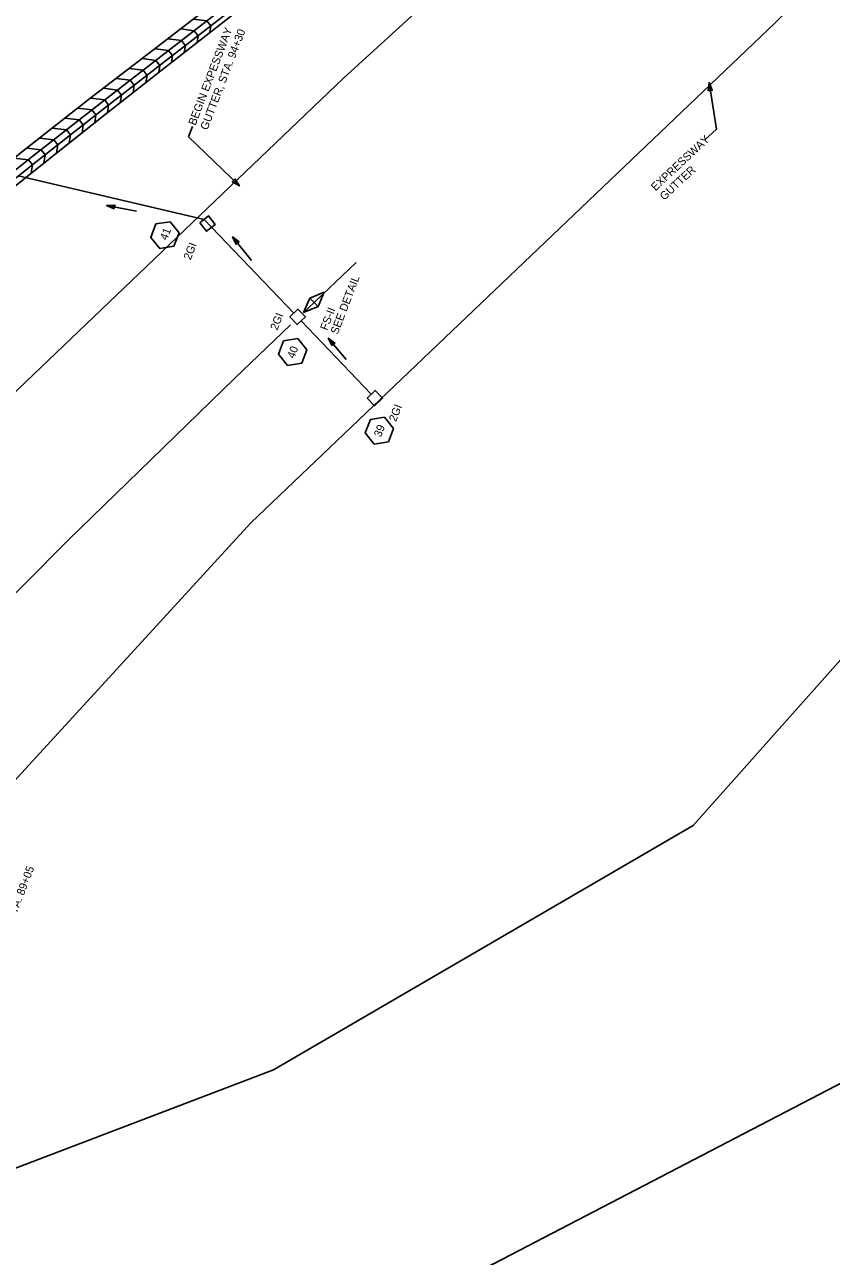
# Model space of a CAD drawing. Extents: x 2384780 to 2405432, y 547869 to 573706.
# Drawn here: x 2396264 to 2396768, y 557527 to 558297 of the extents above; entities that cross this region are included whole.
import ezdxf

# ---------------------------------------------------------------- set-up
doc = ezdxf.new("R2010")
doc.units = 0
for name, color, linetype in [('Old_Level_1', 7, 'Continuous'), ('Old_Level_18', 7, 'Continuous'), ('Old_Level_19', 7, 'Continuous'), ('Old_Level_5', 7, 'Continuous'), ('Old_Level_62', 7, 'Continuous'), ('Old_Level_63', 7, 'Continuous'), ('Old_Level_9', 7, 'Continuous'), ('Prop Drainage Box Number Symbol CELL', 7, 'Continuous')]:
    doc.layers.add(name, color=color, linetype=linetype)

# ---------------------------------------------------------------- blocks, each defined once
blk = doc.blocks.new('FALSUP')
at = {"layer": 'Old_Level_9'}
for p, q in [((0, 0.07375), (-0.181, 0.00325)), ((-0.181, 0.00325), (0, -0.07375)), ((0, -0.07375), (0, 0.07375)), ((0.1775, 0), (0, 0.07375)), ((0, -0.07375), (0.1775, 0))]:
    blk.add_line(p, q, dxfattribs=at)

msp = doc.modelspace()

# ---------------------------------------------------------------- linework, layer by layer
at = {"layer": 'Old_Level_1'}
for p, q in [((2396260.04, 558202.17), (2396376.28, 558175.01)), ((2396432.38, 558116.5), (2396376.28, 558175.01)), ((2396480.66, 558065.71), (2396437.01, 558111.65))]:
    msp.add_line(p, q, dxfattribs=at)
at = {"layer": 'Old_Level_18'}
for p, q in [((2396344.88, 558281.12), (2396384.67, 558311.83)), ((2396388.81, 558307.49), (2396349.08, 558276.71)), ((2396391.56, 558304.59), (2396351.83, 558273.81)), ((2396393.55, 558302.5), (2396353.99, 558271.54)), ((2396304.86, 558250.55), (2396344.88, 558281.12)), ((2396349.08, 558276.71), (2396309.25, 558245.94)), ((2396351.83, 558273.81), (2396312.01, 558243.04)), ((2396314.38, 558240.54), (2396353.99, 558271.54)), ((2396264.98, 558219.35), (2396304.86, 558250.55)), ((2396309.25, 558245.94), (2396269.4, 558214.72)), ((2396312.01, 558243.04), (2396272.17, 558211.83)), ((2396314.38, 558240.54), (2396274.69, 558209.19)), ((2396225.04, 558187.64), (2396264.98, 558219.35)), ((2396272.17, 558211.83), (2396232.32, 558180.1)), ((2396274.69, 558209.19), (2396234.73, 558177.59))]:
    msp.add_line(p, q, dxfattribs=at)
for points in [[(2396110.11, 558084.02), (2396149.75, 558117.8), (2396189.58, 558150.76), (2396229.54, 558182.98), (2396269.4, 558214.72), (2396309.25, 558245.94), (2396349.08, 558276.71), (2396388.81, 558307.49), (2396428.7, 558338.09), (2396468.11, 558369.2), (2396507.43, 558400.42), (2396546.46, 558431.93), (2396585.2, 558463.75), (2396623.66, 558495.86), (2396661.09, 558527.62)], [(2396369.6, 558300.19), (2396378.01, 558299.13), (2396380.49, 558295.93), (2396379.85, 558291.78)], [(2396361.58, 558294.01), (2396370.02, 558292.94), (2396372.5, 558289.74), (2396371.85, 558285.52)], [(2396353.57, 558287.82), (2396362.03, 558286.75), (2396364.51, 558283.55), (2396363.85, 558279.26)], [(2396345.55, 558281.64), (2396354.04, 558280.56), (2396356.52, 558277.36), (2396355.85, 558272.99)], [(2396329.41, 558269.3), (2396338.05, 558268.19), (2396340.53, 558264.99), (2396339.82, 558260.45)], [(2396337.49, 558275.47), (2396346.05, 558274.37), (2396348.52, 558271.17), (2396347.84, 558266.72)], [(2396321.34, 558263.13), (2396330.05, 558262.01), (2396332.53, 558258.81), (2396331.81, 558254.18)], [(2396313.26, 558256.96), (2396322.06, 558255.84), (2396324.53, 558252.63), (2396323.8, 558247.91)], [(2396305.19, 558250.8), (2396314.06, 558249.66), (2396316.53, 558246.45), (2396315.79, 558241.64)], [(2396289.21, 558238.3), (2396298.12, 558237.22), (2396300.62, 558234.04), (2396299.89, 558229.09)], [(2396297.18, 558244.54), (2396306.08, 558243.46), (2396308.57, 558240.27), (2396307.85, 558235.38)], [(2396281.24, 558232.07), (2396290.17, 558230.99), (2396292.66, 558227.8), (2396291.92, 558222.8)], [(2396273.27, 558225.84), (2396282.21, 558224.76), (2396284.71, 558221.57), (2396283.96, 558216.51)], [(2396265.3, 558219.61), (2396274.26, 558218.52), (2396276.75, 558215.34), (2396276, 558210.22)], [(2396257.33, 558213.28), (2396266.32, 558212.26), (2396268.84, 558209.1), (2396268.13, 558204)]]:
    msp.add_lwpolyline(points, dxfattribs=at)
at = {"layer": 'Old_Level_19'}
for points in [[(2396438.32, 558116.7), (2396441.15, 558119.4), (2396471.41, 558148.04)], [(2396059.34, 557724.13), (2396157.46, 557835.98), (2396196.83, 557878.26), (2396236.9, 557919.92), (2396291.11, 557974.52), (2396395.24, 558075.64), (2396430.26, 558109.02)]]:
    msp.add_lwpolyline(points, dxfattribs=at)
at = {"layer": 'Old_Level_5'}
for p, q in [((2396691.97, 558260.47), (2396696.63, 558231.45)), ((2396366.46, 558226.69), (2396369.03, 558233.11)), ((2396689.32, 558224.63), (2396696.63, 558231.45)), ((2396398.26, 558195.91), (2396366.46, 558226.69)), ((2396315.28, 558183.69), (2396333.96, 558180.07)), ((2396394.03, 558164.1), (2396405.94, 558149.22)), ((2396453.83, 558100.76), (2396465.05, 558087.44))]:
    msp.add_line(p, q, dxfattribs=at)
for points in [[(2396691.53, 558255.33), (2396691.97, 558260.47), (2396694, 558255.73)], [(2396395.53, 558200.29), (2396398.26, 558195.91), (2396393.8, 558198.49)], [(2396319.95, 558181.51), (2396315.28, 558183.69), (2396320.42, 558183.97)], [(2396396.18, 558159.41), (2396394.03, 558164.1), (2396398.13, 558160.97)], [(2396456.1, 558096.13), (2396453.83, 558100.76), (2396458.01, 558097.74)]]:
    msp.add_lwpolyline(points, close=True, dxfattribs=at)
at = {"layer": 'Old_Level_62'}
for points in [[(2396419.7, 557643.47), (2396682.04, 557796.2), (2396828.18, 557960.29), (2396996.36, 558095.15), (2397094.89, 558211.04), (2397313.65, 558336.89), (2397384.14, 558347.22), (2397601.34, 558506.89), (2397752.86, 558571.29), (2397581.56, 558655.74), (2397315.55, 558710.07), (2397180.39, 558737.03), (2396733.28, 558297.93), (2396405.46, 557985.46), (2396072.95, 557622.86), (2396164.14, 557546.31)], [(2396034.81, 558046.95), (2396309.7, 558569.81), (2396830.12, 558678.33), (2396873.09, 558636.56), (2396463.4, 558263.16), (2396226.67, 558037.32), (2395950.25, 557725.64), (2395851.08, 557814.24)]]:
    msp.add_lwpolyline(points, close=True, dxfattribs=at)
at = {"layer": 'Old_Level_63'}
msp.add_lwpolyline([(2396099.2, 557284.37), (2397844.02, 558190.9), (2398327.16, 558239.39)], dxfattribs=at)
at = {"layer": 'Old_Level_9'}
for points in [[(2396373.51, 558172.84), (2396379.04, 558177.17), (2396383.18, 558171.88), (2396377.65, 558167.57)], [(2396429.84, 558114.07), (2396434.92, 558118.92), (2396439.55, 558114.06), (2396434.47, 558109.23)], [(2396478.12, 558063.29), (2396483.21, 558068.14), (2396487.84, 558063.28), (2396482.75, 558058.45)]]:
    msp.add_lwpolyline(points, close=True, dxfattribs=at)
at = {"layer": 'Prop Drainage Box Number Symbol CELL'}
for points in [[(2396354.91, 558173.54), (2396346.07, 558172.14), (2396342.86, 558163.79), (2396348.49, 558156.83), (2396357.33, 558158.23), (2396360.54, 558166.59)], [(2396434.81, 558100.47), (2396425.97, 558099.07), (2396422.76, 558090.72), (2396428.39, 558083.76), (2396437.23, 558085.16), (2396440.44, 558093.52)], [(2396489.01, 558051.32), (2396480.17, 558049.92), (2396476.97, 558041.56), (2396482.6, 558034.61), (2396491.44, 558036.01), (2396494.64, 558044.36)]]:
    msp.add_lwpolyline(points, close=True, dxfattribs=at)

# ---------------------------------------------------------------- block references
at = {"layer": 'Old_Level_9', "xscale": 49.99999999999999, "yscale": 49.999999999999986, "rotation": 45.24857468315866}
msp.add_blockref('FALSUP', (2396444.96, 558123.19), dxfattribs=at)

# ---------------------------------------------------------------- texts
at = {"layer": 'Old_Level_5'}
for s, rotation, p in [('BEGIN EXPESSWAY', 69.00009, (2396370.79, 558233.37)), ('GUTTER, STA. 94+30', 69.00009, (2396378.26, 558230.5)), ('EXPRESSWAY ', 43.00001, (2396658.48, 558192.46)), ('GUTTER', 43.00001, (2396663.94, 558186.61)), ('2GI', 69.00009, (2396367.79, 558149.3)), ('SEE DETAIL', 69.00009, (2396459.75, 558102.77)), ('2GI', 69.00009, (2396422.01, 558105.35)), ('FS-II', 69.00009, (2396453.22, 558105.28)), ('2GI', 69.00009, (2396496.24, 558048.19))]:
    msp.add_text(s, height=5, rotation=rotation, dxfattribs=at).set_placement(p)
at = {"layer": 'Old_Level_63'}
msp.add_text('GUTTER, STA. 89+05', height=5, rotation=69.00009, dxfattribs=at).set_placement((2396246.24, 557707.45))
at = {"layer": 'Prop Drainage Box Number Symbol CELL'}
for s, p in [('41', (2396353, 558161.59)), ('40', (2396432.57, 558087.67)), ('39', (2396486.8, 558038.57))]:
    msp.add_text(s, height=5, rotation=69.00009, dxfattribs=at).set_placement(p)

doc.saveas('drawing.dxf')
